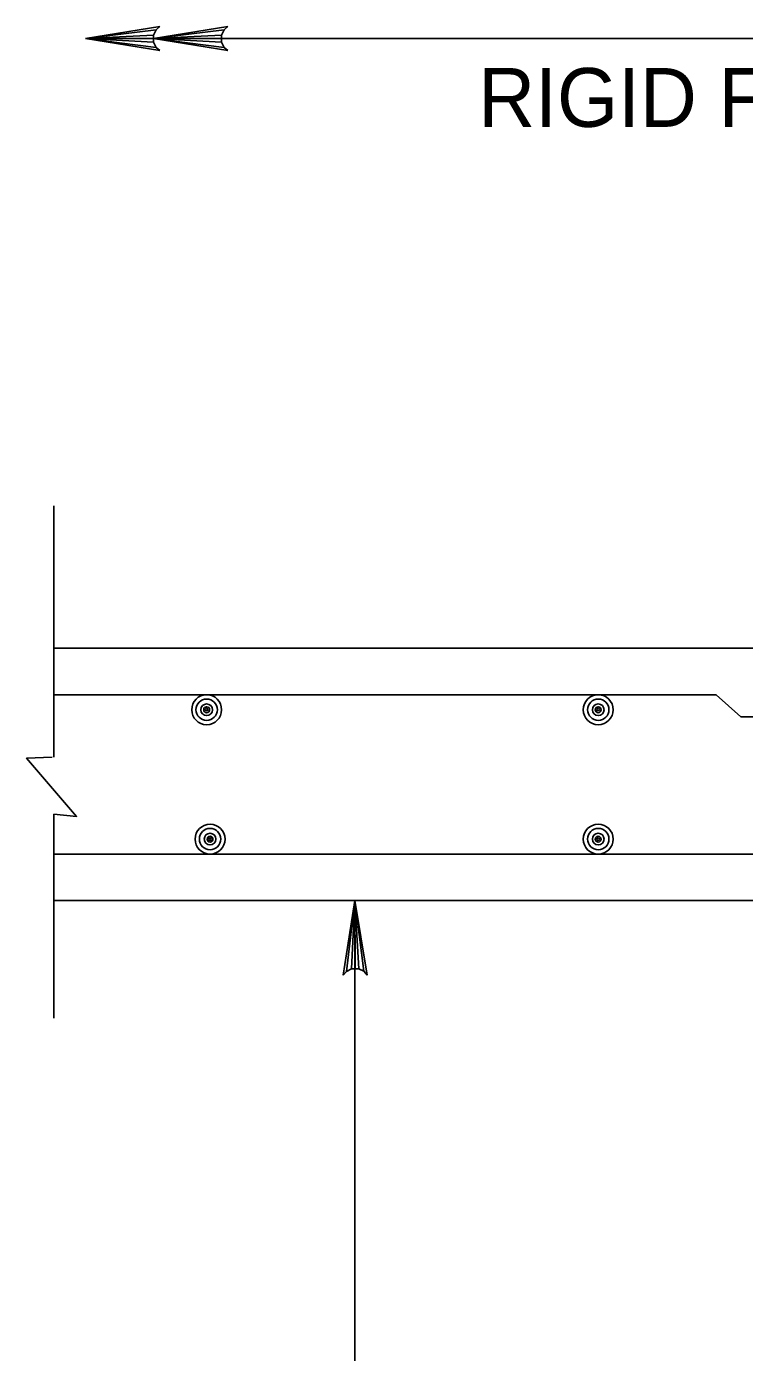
# Model space of a CAD drawing. Extents: x 641328 to 643024, y 298283 to 300065.
# Drawn here: x 641509.5 to 641546.1, y 299951.5 to 300019.1 of the extents above; entities that cross this region are included whole.
import ezdxf

# ---------------------------------------------------------------- set-up
doc = ezdxf.new("R2010")
doc.units = 0
doc.layers.add('2', color=7, linetype='Continuous')

msp = doc.modelspace()

# ---------------------------------------------------------------- linework, layer by layer
at = {"layer": '2'}
for p, q in [((641512.492, 300018.485), (641516.289, 300019.102)), ((641516.092, 300018.927), (641512.492, 300018.485)), ((641512.492, 300018.485), (641515.964, 300018.665)), ((641515.964, 300018.485), (641519.761, 300019.102)), ((641515.964, 300018.665), (641516.092, 300018.927)), ((641519.564, 300018.927), (641515.964, 300018.485)), ((641515.964, 300018.304), (641515.964, 300018.665)), ((641515.964, 300018.485), (641519.436, 300018.665)), ((641516.289, 300019.102), (641516.092, 300018.927)), ((641519.436, 300018.665), (641519.564, 300018.927)), ((641519.437, 300018.304), (641519.436, 300018.665)), ((641519.761, 300019.102), (641519.564, 300018.927)), ((641512.492, 300018.485), (641587.3, 300018.485)), ((641515.964, 300018.304), (641512.492, 300018.485)), ((641512.492, 300018.485), (641516.099, 300018.038)), ((641516.291, 300017.878), (641512.492, 300018.485)), ((641512.492, 300018.485), (641515.964, 300018.485)), ((641519.437, 300018.304), (641515.964, 300018.485)), ((641515.964, 300018.485), (641519.572, 300018.038)), ((641519.763, 300017.878), (641515.964, 300018.485)), ((641515.964, 300018.485), (641519.436, 300018.485)), ((641516.099, 300018.038), (641515.964, 300018.304)), ((641516.099, 300018.038), (641516.291, 300017.878)), ((641519.572, 300018.038), (641519.437, 300018.304)), ((641519.572, 300018.038), (641519.763, 300017.878)), ((641510.875, 299981.846), (641510.875, 299994.653)), ((641510.875, 299987.398), (641587.3, 299987.398)), ((641510.875, 299985.023), (641544.675, 299985.023)), ((641544.675, 299985.023), (641545.925, 299983.898)), ((641563.05, 299983.898), (641545.925, 299983.898)), ((641510.875, 299968.523), (641510.875, 299978.933)), ((641510.875, 299976.898), (641586.3, 299976.898)), ((641510.875, 299974.523), (641572.358, 299974.523)), ((641510.98, 299974.523), (641541.863, 299974.523)), ((641525.645, 299970.721), (641526.236, 299974.523)), ((641526.236, 299974.523), (641525.805, 299970.913)), ((641526.07, 299971.049), (641526.236, 299974.523)), ((641526.236, 299904.968), (641526.236, 299974.523)), ((641526.236, 299974.523), (641526.432, 299971.052)), ((641526.694, 299970.924), (641526.236, 299974.523)), ((641526.236, 299974.523), (641526.87, 299970.728)), ((641526.236, 299974.523), (641526.251, 299971.05)), ((641525.805, 299970.913), (641525.645, 299970.721)), ((641525.805, 299970.913), (641526.07, 299971.049)), ((641526.07, 299971.049), (641526.432, 299971.052)), ((641526.432, 299971.052), (641526.694, 299970.924)), ((641526.87, 299970.728), (641526.694, 299970.924))]:
    msp.add_line(p, q, dxfattribs=at)
msp.add_lwpolyline([(641510.875, 299978.933), (641512.036, 299978.816), (641509.485, 299981.789), (641510.796, 299981.833)], dxfattribs=at)
for centre, radius in [((641518.676, 299984.26), 0.763), ((641518.676, 299984.26), 0.545), ((641538.651, 299984.26), 0.763), ((641538.651, 299984.26), 0.545), ((641518.676, 299984.26), 0.298), ((641518.676, 299984.26), 0.15), ((641518.676, 299984.26), 0.0644), ((641538.651, 299984.26), 0.298), ((641538.651, 299984.26), 0.15), ((641538.651, 299984.26), 0.0644), ((641518.849, 299977.661), 0.763), ((641518.849, 299977.661), 0.545), ((641518.849, 299977.661), 0.298), ((641538.651, 299977.661), 0.763), ((641538.651, 299977.661), 0.545), ((641538.651, 299977.661), 0.298), ((641518.849, 299977.661), 0.15), ((641518.849, 299977.661), 0.0644), ((641538.651, 299977.661), 0.15), ((641538.651, 299977.661), 0.0644)]:
    msp.add_circle(centre, radius, dxfattribs=at)

# ---------------------------------------------------------------- texts
msp.add_text('RIGID FRAME', height=2.99999, dxfattribs=at).set_placement((641532.537, 300013.985))

doc.saveas('drawing.dxf')
